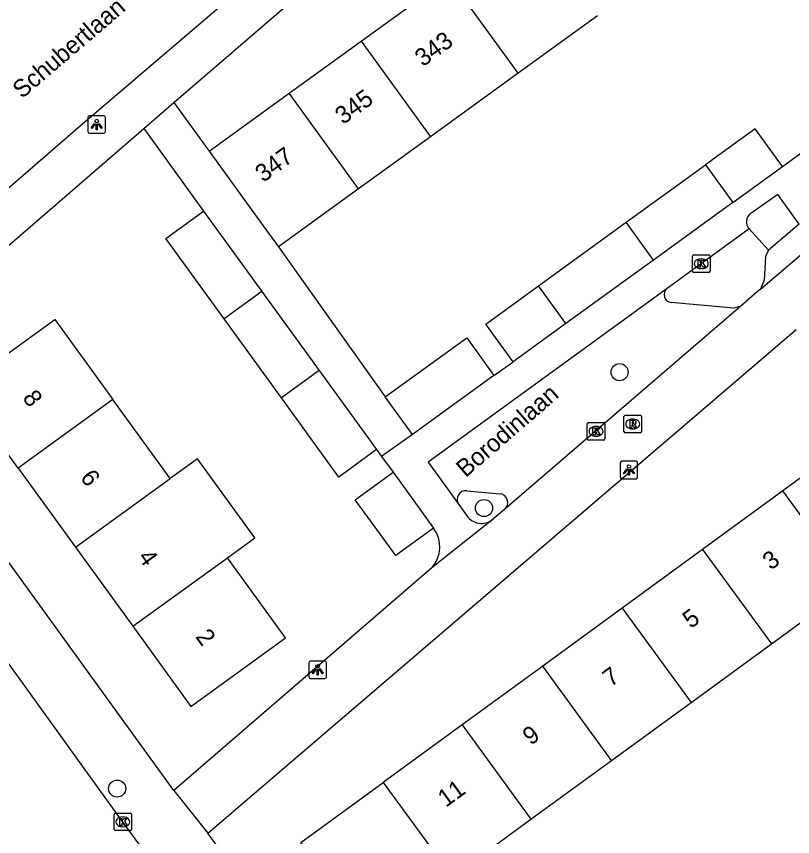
# Model space of a CAD drawing. Extents: x 159040 to 160094, y 381214 to 382518.
# Drawn here: x 159252.34 to 159296.66, y 381414.52 to 381461.36 of the extents above; entities that cross this region are included whole.
import ezdxf

# ---------------------------------------------------------------- set-up
doc = ezdxf.new("R2010")
doc.units = 0
for name, color, linetype in [('IMGEO_Boom', 7, 'Continuous'), ('IMGEO_Kolk', 7, 'Continuous'), ('IMGEO_Lichtpunt', 7, 'Continuous'), ('IMGEO_Openbare_ruimte_label', 7, 'Continuous'), ('IMGEO_Pand', 7, 'Continuous'), ('IMGEO_Pand_nummerreeks', 7, 'Continuous'), ('IMGEO_Parkeervlak_open', 7, 'Continuous'), ('IMGEO_Rijbaan_lokaal_gesloten', 7, 'Continuous'), ('IMGEO_Rijbaan_lokaal_open', 7, 'Continuous'), ('IMGEO_Rioolput', 7, 'Continuous'), ('IMGEO_Voetpad_open', 7, 'Continuous')]:
    doc.layers.add(name, color=color, linetype=linetype)

msp = doc.modelspace()

# ---------------------------------------------------------------- linework, layer by layer
at = {"layer": 'IMGEO_Boom'}
for centre in [(159286.783, 381441.043), (159279.042, 381433.281), (159258.088, 381417.26)]:
    msp.add_circle(centre, 0.489, dxfattribs=at)
at = {"layer": 'IMGEO_Kolk'}
for p, q in [((159290.947, 381446.808), (159290.947, 381447.66)), ((159291.022, 381447.734), (159291.874, 381447.734)), ((159291.435, 381447.514), (159291.46, 381447.514)), ((159291.948, 381447.66), (159291.948, 381446.808)), ((159291.874, 381446.734), (159291.022, 381446.734)), ((159291.458, 381446.954), (159291.433, 381446.954)), ((159285.013, 381438.161), (159285.865, 381438.161)), ((159284.938, 381437.235), (159284.938, 381438.087)), ((159285.426, 381437.941), (159285.451, 381437.941)), ((159285.939, 381438.087), (159285.939, 381437.235)), ((159285.865, 381437.161), (159285.013, 381437.161)), ((159285.449, 381437.381), (159285.424, 381437.381)), ((159257.912, 381414.932), (159257.912, 381415.784)), ((159257.987, 381415.858), (159258.839, 381415.858)), ((159258.4, 381415.638), (159258.425, 381415.638)), ((159258.913, 381415.784), (159258.913, 381414.932)), ((159258.839, 381414.858), (159257.987, 381414.858)), ((159258.423, 381415.078), (159258.398, 381415.078))]:
    msp.add_line(p, q, dxfattribs=at)
for points in [[(159290.947, 381446.808), (159290.947, 381447.66)], [(159291.022, 381447.734), (159291.874, 381447.734)], [(159291.948, 381447.66), (159291.948, 381446.808)], [(159291.268, 381447.434), (159291.391, 381447.434), (159291.391, 381447.283), (159291.521, 381447.434), (159291.685, 381447.434), (159291.539, 381447.283), (159291.692, 381447.034), (159291.54, 381447.034), (159291.455, 381447.198), (159291.391, 381447.131), (159291.391, 381447.034), (159291.268, 381447.034), (159291.268, 381447.434)], [(159291.874, 381446.734), (159291.022, 381446.734)], [(159285.013, 381438.161), (159285.865, 381438.161)], [(159284.938, 381437.235), (159284.938, 381438.087)], [(159285.259, 381437.861), (159285.382, 381437.861), (159285.382, 381437.71), (159285.512, 381437.861), (159285.676, 381437.861), (159285.53, 381437.71), (159285.683, 381437.461), (159285.531, 381437.461), (159285.446, 381437.625), (159285.382, 381437.558), (159285.382, 381437.461), (159285.259, 381437.461), (159285.259, 381437.861)], [(159285.939, 381438.087), (159285.939, 381437.235)], [(159285.865, 381437.161), (159285.013, 381437.161)], [(159257.912, 381414.932), (159257.912, 381415.784)], [(159257.987, 381415.858), (159258.839, 381415.858)], [(159258.913, 381415.784), (159258.913, 381414.932)], [(159258.233, 381415.558), (159258.356, 381415.558), (159258.356, 381415.407), (159258.486, 381415.558), (159258.65, 381415.558), (159258.504, 381415.407), (159258.657, 381415.158), (159258.505, 381415.158), (159258.42, 381415.322), (159258.356, 381415.255), (159258.356, 381415.158), (159258.233, 381415.158), (159258.233, 381415.558)], [(159258.839, 381414.858), (159257.987, 381414.858)]]:
    msp.add_lwpolyline(points, dxfattribs=at)
for centre, start, end in [((159291.024, 381447.658), 91.552, 178.448), ((159291.024, 381447.658), 91.552, 178.448), ((159291.872, 381447.658), 1.552, 88.448), ((159291.872, 381447.658), 1.552, 88.448), ((159291.024, 381446.81), 181.552, 268.448), ((159291.024, 381446.81), 181.552, 268.448), ((159291.872, 381446.81), 271.552, 358.448), ((159291.872, 381446.81), 271.552, 358.448), ((159285.015, 381438.085), 91.552, 178.448), ((159285.015, 381438.085), 91.552, 178.448), ((159285.863, 381438.085), 1.552, 88.448), ((159285.863, 381438.085), 1.552, 88.448), ((159285.015, 381437.237), 181.552, 268.448), ((159285.015, 381437.237), 181.552, 268.448), ((159285.863, 381437.237), 271.552, 358.448), ((159285.863, 381437.237), 271.552, 358.448), ((159257.989, 381415.782), 91.552, 178.448), ((159257.989, 381415.782), 91.552, 178.448), ((159258.837, 381415.782), 1.552, 88.448), ((159258.837, 381415.782), 1.552, 88.448), ((159257.989, 381414.934), 181.552, 268.448), ((159257.989, 381414.934), 181.552, 268.448), ((159258.837, 381414.934), 271.552, 358.448), ((159258.837, 381414.934), 271.552, 358.448)]:
    msp.add_arc(centre, 0.0765, start, end, dxfattribs=at)
for centre, major_axis, ratio, start_param, end_param in [((159291.434, 381447.234), (-0.387, 0.002), 0.722429, 4.712389, 7.853982), ((159291.459, 381447.234), (-0.39, 0.002), 0.717154, 1.570796, 4.712389), ((159285.425, 381437.661), (-0.387, 0.002), 0.722429, 4.712389, 7.853982), ((159285.45, 381437.661), (-0.39, 0.002), 0.717154, 1.570796, 4.712389), ((159258.399, 381415.358), (-0.387, 0.002), 0.722429, 4.712389, 7.853982), ((159258.424, 381415.358), (-0.39, 0.002), 0.717154, 1.570796, 4.712389)]:
    msp.add_ellipse(centre, major_axis=major_axis, ratio=ratio, start_param=start_param, end_param=end_param, dxfattribs=at)
at = {"layer": 'IMGEO_Lichtpunt'}
for p, q in [((159256.419, 381455.588), (159256.419, 381454.781)), ((159256.419, 381455.588), (159256.419, 381454.781)), ((159257.321, 381455.683), (159256.513, 381455.683)), ((159257.321, 381455.683), (159256.513, 381455.683)), ((159257.415, 381454.781), (159257.415, 381455.588)), ((159257.415, 381454.781), (159257.415, 381455.588)), ((159256.513, 381454.687), (159257.321, 381454.687)), ((159256.513, 381454.687), (159257.321, 381454.687)), ((159286.819, 381435.859), (159286.819, 381435.052)), ((159286.819, 381435.859), (159286.819, 381435.052)), ((159287.721, 381435.954), (159286.913, 381435.954)), ((159287.721, 381435.954), (159286.913, 381435.954)), ((159287.815, 381435.052), (159287.815, 381435.859)), ((159287.815, 381435.052), (159287.815, 381435.859)), ((159286.913, 381434.958), (159287.721, 381434.958)), ((159286.913, 381434.958), (159287.721, 381434.958)), ((159269.944, 381424.541), (159269.136, 381424.541)), ((159269.944, 381424.541), (159269.136, 381424.541)), ((159269.042, 381424.446), (159269.042, 381423.639)), ((159269.042, 381424.446), (159269.042, 381423.639)), ((159270.038, 381423.639), (159270.038, 381424.446)), ((159270.038, 381423.639), (159270.038, 381424.446)), ((159269.136, 381423.545), (159269.944, 381423.545)), ((159269.136, 381423.545), (159269.944, 381423.545))]:
    msp.add_line(p, q, dxfattribs=at)
for points in [[(159256.793, 381455.252), (159256.832, 381455.224), (159256.644, 381454.962), (159256.606, 381454.989), (159256.793, 381455.252)], [(159256.895, 381455.204), (159256.942, 381455.204), (159256.942, 381454.882), (159256.895, 381454.882), (159256.895, 381455.204)], [(159257.005, 381455.224), (159257.043, 381455.251), (159257.23, 381454.989), (159257.191, 381454.961), (159257.005, 381455.224)], [(159287.193, 381435.523), (159287.232, 381435.495), (159287.044, 381435.233), (159287.006, 381435.26), (159287.193, 381435.523)], [(159287.295, 381435.475), (159287.342, 381435.475), (159287.342, 381435.153), (159287.295, 381435.153), (159287.295, 381435.475)], [(159287.405, 381435.495), (159287.443, 381435.522), (159287.63, 381435.26), (159287.591, 381435.232), (159287.405, 381435.495)], [(159269.416, 381424.11), (159269.455, 381424.082), (159269.267, 381423.82), (159269.229, 381423.847), (159269.416, 381424.11)], [(159269.518, 381424.062), (159269.565, 381424.062), (159269.565, 381423.74), (159269.518, 381423.74), (159269.518, 381424.062)], [(159269.628, 381424.082), (159269.666, 381424.109), (159269.853, 381423.847), (159269.814, 381423.819), (159269.628, 381424.082)]]:
    msp.add_lwpolyline(points, dxfattribs=at)
for centre in [(159256.918, 381455.386), (159287.318, 381435.657), (159269.541, 381424.244)]:
    msp.add_circle(centre, 0.0994, dxfattribs=at)
for centre, start, end in [((159256.513, 381455.588), 90, 180), ((159256.513, 381455.588), 90, 180), ((159257.321, 381455.588), 0, 90), ((159257.321, 381455.588), 0, 90), ((159256.513, 381454.781), 180, 270), ((159256.513, 381454.781), 180, 270), ((159257.321, 381454.781), 270, 0), ((159257.321, 381454.781), 270, 360), ((159286.913, 381435.859), 90, 180), ((159286.913, 381435.859), 90, 180), ((159287.721, 381435.859), 0, 90), ((159287.721, 381435.859), 0, 90), ((159286.913, 381435.052), 180, 270), ((159286.913, 381435.052), 180, 270), ((159287.721, 381435.052), 270, 0), ((159287.721, 381435.052), 270, 360), ((159269.136, 381424.446), 90, 180), ((159269.136, 381424.446), 90, 180), ((159269.944, 381424.446), 0, 90), ((159269.944, 381424.446), 0, 90), ((159269.136, 381423.639), 180, 270), ((159269.136, 381423.639), 180, 270), ((159269.944, 381423.639), 270, 0), ((159269.944, 381423.639), 270, 360)]:
    msp.add_arc(centre, 0.0946, start, end, dxfattribs=at)
at = {"layer": 'IMGEO_Pand'}
for points in [[(159272.018, 381459.943), (159277.031, 381463.576)], [(159280.992, 381458.111), (159277.031, 381463.576)], [(159285.524, 381461.395), (159280.992, 381458.111)], [(159267.921, 381456.974), (159272.018, 381459.943)], [(159272.018, 381459.943), (159275.979, 381454.478)], [(159280.992, 381458.111), (159275.979, 381454.478)], [(159263.349, 381453.661), (159267.921, 381456.974)], [(159271.882, 381451.509), (159267.921, 381456.974)], [(159296.091, 381452.788), (159294.53, 381454.94), (159291.693, 381452.884)], [(159275.979, 381454.478), (159271.882, 381451.509)], [(159263.349, 381453.661), (159266.284, 381449.613), (159267.307, 381448.194)], [(159287.161, 381449.6), (159291.693, 381452.884)], [(159291.693, 381452.884), (159293.253, 381450.732)], [(159293.253, 381450.732), (159296.091, 381452.788)], [(159271.882, 381451.509), (159267.307, 381448.194)], [(159293.253, 381450.732), (159288.721, 381447.447)], [(159264.199, 381444.09), (159260.87, 381448.683), (159263.028, 381450.246)], [(159263.028, 381450.246), (159266.356, 381445.654)], [(159282.148, 381445.967), (159287.161, 381449.6)], [(159288.721, 381447.447), (159287.161, 381449.6)], [(159288.721, 381447.447), (159283.708, 381443.814)], [(159266.356, 381445.654), (159264.199, 381444.09)], [(159266.356, 381445.654), (159269.63, 381441.136)], [(159280.705, 381441.638), (159279.145, 381443.791), (159282.148, 381445.967)], [(159283.708, 381443.814), (159282.148, 381445.967)], [(159252.438, 381435.563), (159249.12, 381440.142), (159254.524, 381444.059), (159257.842, 381439.481)], [(159267.473, 381439.572), (159264.199, 381444.09)], [(159283.708, 381443.814), (159280.705, 381441.638)], [(159273.401, 381439.628), (159278.051, 381442.998), (159279.611, 381440.845)], [(159269.63, 381441.136), (159267.473, 381439.572)], [(159269.63, 381441.136), (159272.905, 381436.617)], [(159279.611, 381440.845), (159274.961, 381437.475)], [(159272.905, 381436.617), (159270.748, 381435.053), (159267.473, 381439.572)], [(159274.961, 381437.475), (159273.401, 381439.628)], [(159257.842, 381439.481), (159252.438, 381435.563)], [(159261.116, 381434.963), (159257.842, 381439.481)], [(159300.05, 381428.882), (159301.818, 381426.459), (159306.259, 381429.7), (159304.49, 381432.123), (159300.556, 381437.513), (159296.116, 381434.272)], [(159264.39, 381430.444), (159265.95, 381431.574), (159262.675, 381436.093), (159261.116, 381434.963)], [(159252.438, 381435.563), (159255.712, 381431.045)], [(159276.155, 381432.133), (159273.997, 381430.569), (159271.687, 381433.757), (159273.844, 381435.322)], [(159273.844, 381435.322), (159276.155, 381432.133)], [(159255.712, 381431.045), (159261.116, 381434.963)], [(159296.116, 381434.272), (159291.522, 381430.92)], [(159300.05, 381428.882), (159296.116, 381434.272)], [(159255.712, 381431.045), (159258.987, 381426.527)], [(159291.522, 381430.92), (159286.93, 381427.569)], [(159291.522, 381430.92), (159295.456, 381425.529)], [(159258.987, 381426.527), (159264.39, 381430.444)], [(159258.987, 381426.527), (159262.304, 381421.949), (159267.708, 381425.866), (159264.39, 381430.444)], [(159295.456, 381425.529), (159300.05, 381428.882)], [(159286.93, 381427.569), (159282.391, 381424.255)], [(159286.93, 381427.569), (159290.865, 381422.178)], [(159290.865, 381422.178), (159295.456, 381425.529)], [(159282.391, 381424.255), (159277.786, 381420.895)], [(159286.325, 381418.865), (159282.391, 381424.255)], [(159286.325, 381418.865), (159290.865, 381422.178)], [(159277.786, 381420.895), (159273.286, 381417.611)], [(159277.786, 381420.895), (159281.721, 381415.504)], [(159281.721, 381415.504), (159286.325, 381418.865)], [(159277.221, 381412.22), (159272.515, 381408.785), (159268.58, 381414.176), (159273.286, 381417.611)], [(159273.286, 381417.611), (159277.221, 381412.22)], [(159277.221, 381412.22), (159281.721, 381415.504)]]:
    msp.add_lwpolyline(points, dxfattribs=at)
at = {"layer": 'IMGEO_Parkeervlak_open'}
for points in [[(159297.045, 381449.492), (159295.297, 381448)], [(159278.053, 381434.272), (159279.942, 381434.1)]]:
    msp.add_lwpolyline(points, dxfattribs=at)
for centre, radius, start, end in [((159278.008, 381433.774), 0.5, 84.8403, 214.3826), ((159279.895, 381433.601), 0.501, 311.4252, 84.5771)]:
    msp.add_arc(centre, radius, start, end, dxfattribs=at)
at = {"layer": 'IMGEO_Rijbaan_lokaal_gesloten'}
for points in [[(159277.501, 381473.611), (159272.134, 381469.012), (159266.909, 381464.432), (159256.003, 381455.11), (159249.106, 381449.157), (159247.332, 381447.733), (159245.979, 381446.609)], [(159294.711, 381365.624), (159293.71, 381366.959), (159292.46, 381368.626), (159288.626, 381373.873), (159279.327, 381386.65), (159278.393, 381387.933), (159276.984, 381389.893), (159273.822, 381394.288), (159272.056, 381396.709), (159266.652, 381404.115), (159260.931, 381411.92), (159258.606, 381415.092), (159258.439, 381415.32), (159246.108, 381432.406), (159245.1, 381433.81)]]:
    msp.add_lwpolyline(points, dxfattribs=at)
at = {"layer": 'IMGEO_Rijbaan_lokaal_open'}
for points in [[(159294.831, 381445.789), (159308.398, 381457.371)], [(159296.091, 381452.788), (159297.79, 381454.02), (159298.801, 381454.752)], [(159297.045, 381449.492), (159295.82, 381451.182), (159294.278, 381450.108)], [(159294.182, 381449.224), (159289.502, 381445.822)], [(159289.502, 381445.822), (159275.851, 381435.902), (159277.595, 381433.491)], [(159294.831, 381445.789), (159294.662, 381445.645), (159293.7, 381444.812)], [(159293.7, 381444.812), (159280.226, 381433.226)], [(159263.262, 381414.719), (159296.875, 381443.481)], [(159279.611, 381440.845), (159280.705, 381441.638)], [(159274.961, 381437.475), (159273.189, 381436.226)], [(159273.189, 381436.226), (159273.844, 381435.322)], [(159277.595, 381433.491), (159278.082, 381432.818)], [(159280.226, 381433.226), (159279.48, 381432.596)], [(159279.48, 381432.596), (159276.058, 381429.872)], [(159276.058, 381429.872), (159261.321, 381417.145)], [(159261.321, 381417.145), (159263.262, 381414.719)]]:
    msp.add_lwpolyline(points, dxfattribs=at)
for centre, radius, start, end in [((159294.627, 381449.623), 0.598, 125.766, 221.8382), ((159278.892, 381433.404), 1, 215.913, 306.0408), ((159274.733, 381431.061), 1.78, 318.0781, 37.0087)]:
    msp.add_arc(centre, radius, start, end, dxfattribs=at)
at = {"layer": 'IMGEO_Rioolput'}
for p, q in [((159287.108, 381438.578), (159287.96, 381438.578)), ((159287.033, 381437.652), (159287.033, 381438.504)), ((159287.521, 381438.358), (159287.546, 381438.358)), ((159288.034, 381438.504), (159288.034, 381437.652)), ((159287.544, 381437.798), (159287.519, 381437.798)), ((159287.96, 381437.578), (159287.108, 381437.578))]:
    msp.add_line(p, q, dxfattribs=at)
for points in [[(159287.108, 381438.578), (159287.96, 381438.578)], [(159287.033, 381437.652), (159287.033, 381438.504)], [(159287.622, 381438.276), (159287.37, 381438.278), (159287.37, 381437.878)], [(159287.548, 381438.197), (159287.494, 381438.197), (159287.494, 381438.116)], [(159287.494, 381438.116), (159287.546, 381438.116)], [(159288.034, 381438.504), (159288.034, 381437.652)], [(159287.37, 381437.878), (159287.494, 381437.878), (159287.494, 381438.04), (159287.505, 381438.04)], [(159287.552, 381438.011), (159287.623, 381437.878), (159287.763, 381437.878), (159287.698, 381438.004)], [(159287.96, 381437.578), (159287.108, 381437.578)]]:
    msp.add_lwpolyline(points, dxfattribs=at)
for centre, radius, start, end in [((159287.11, 381438.502), 0.0765, 91.552, 178.448), ((159287.11, 381438.502), 0.0765, 91.552, 178.448), ((159287.958, 381438.502), 0.0765, 1.552, 88.448), ((159287.958, 381438.502), 0.0765, 1.552, 88.448), ((159287.53, 381438.305), 0.19, 274.7715, 282.9687), ((159287.554, 381438.101), 0.0964, 77.0061, 93.1865), ((159287.568, 381438.158), 0.0378, 276.6634, 79.6772), ((159287.621, 381438.166), 0.109, 350.3612, 89.416), ((159287.619, 381438.166), 0.112, 277.5842, 350.9817), ((159287.11, 381437.654), 0.0765, 181.552, 268.448), ((159287.11, 381437.654), 0.0765, 181.552, 268.448), ((159287.504, 381437.987), 0.0533, 26.0293, 88.6989), ((159287.603, 381437.951), 0.108, 29.5134, 73.7905), ((159287.958, 381437.654), 0.0765, 271.552, 358.448), ((159287.958, 381437.654), 0.0765, 271.552, 358.448)]:
    msp.add_arc(centre, radius, start, end, dxfattribs=at)
for centre, major_axis, ratio, start_param, end_param in [((159287.52, 381438.078), (-0.387, 0.002), 0.722429, 4.712389, 7.853982), ((159287.545, 381438.078), (-0.39, 0.002), 0.717154, 1.570796, 4.712389)]:
    msp.add_ellipse(centre, major_axis=major_axis, ratio=ratio, start_param=start_param, end_param=end_param, dxfattribs=at)
at = {"layer": 'IMGEO_Voetpad_open'}
for points in [[(159261.335, 381456.439), (159271.679, 381465.369), (159291.22, 381481.993)], [(159259.615, 381454.955), (159261.335, 381456.439)], [(159261.335, 381456.439), (159263.349, 381453.661)], [(159247.758, 381444.719), (159259.615, 381454.955)], [(159259.615, 381454.955), (159263.028, 381450.246)], [(159295.297, 381448), (159294.182, 381449.224)], [(159267.307, 381448.194), (159273.401, 381439.628)], [(159295.297, 381448), (159295.122, 381447.647), (159295.047, 381446.293), (159294.831, 381445.789)], [(159293.7, 381444.812), (159293.308, 381444.692), (159289.735, 381445.017)], [(159261.321, 381417.145), (159246.508, 381437.599)], [(159272.905, 381436.617), (159273.189, 381436.226)], [(159276.645, 381396.319), (159276.617, 381396.357), (159275.173, 381398.343), (159263.262, 381414.719)]]:
    msp.add_lwpolyline(points, dxfattribs=at)
msp.add_arc((159289.776, 381445.465), 0.45, 127.4977, 264.7875, dxfattribs=at)

# ---------------------------------------------------------------- texts
at = {"layer": 'IMGEO_Openbare_ruimte_label'}
for s, rotation, p in [('Schubertlaan', 40.5392, (159252.65, 381456.625)), ('Borodinlaan', 40.9057, (159277.991, 381434.99))]:
    msp.add_text(s, height=1, rotation=rotation, dxfattribs=at).set_placement(p)
at = {"layer": 'IMGEO_Pand_nummerreeks'}
for s, rotation, p in [('343', 35.9307, (159275.552, 381458.454)), ('345', 35.9307, (159270.994, 381455.151)), ('347', 35.9307, (159266.437, 381451.848)), ('8', 305.9299, (159252.649, 381439.567)), ('6', 305.9299, (159255.943, 381435.021)), ('4', 305.9299, (159259.239, 381430.473)), ('3', 36.123, (159295.416, 381429.701)), ('5', 36.123, (159290.848, 381426.367)), ('2', 305.9299, (159262.533, 381425.926)), ('7', 36.123, (159286.28, 381423.033)), ('9', 36.123, (159281.712, 381419.699)), ('11', 36.123, (159276.864, 381416.16))]:
    msp.add_text(s, height=1, rotation=rotation, dxfattribs=at).set_placement(p)

doc.saveas('drawing.dxf')
